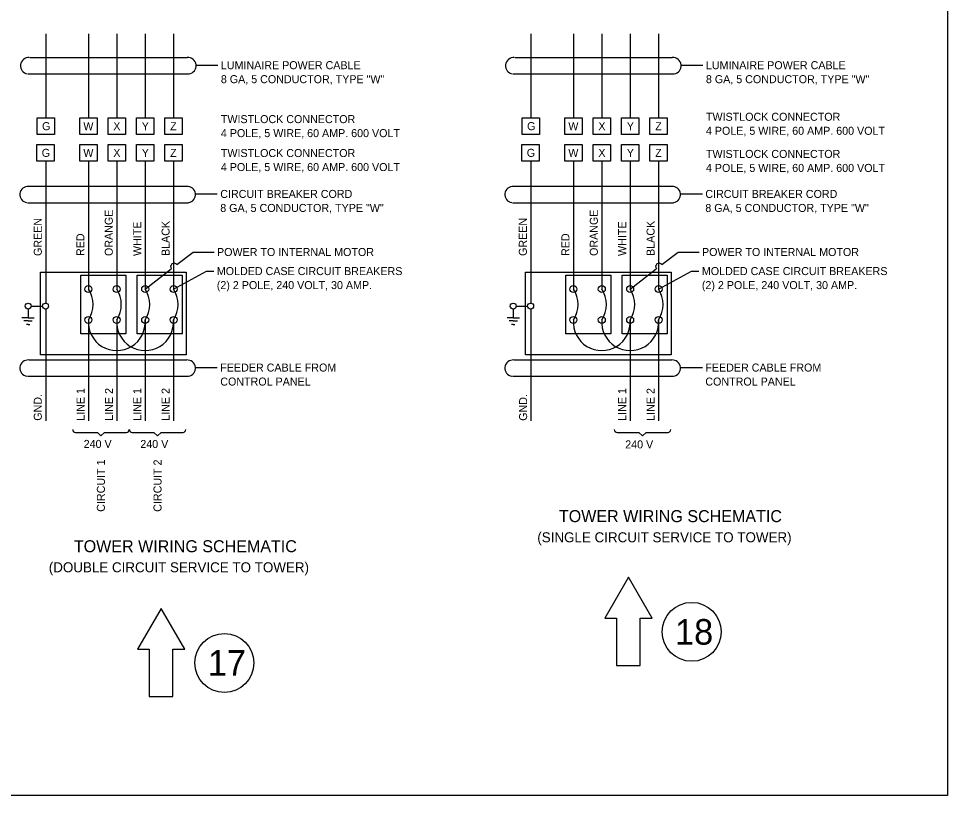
# Model space of a CAD drawing. Extents: x 99981 to 128681, y 99783 to 102182.
# Drawn here: x 122189 to 123581, y 99887 to 101052 of the extents above; entities that cross this region are included whole.
import ezdxf

# ---------------------------------------------------------------- set-up
doc = ezdxf.new("R2010")
doc.units = 0
for name, color, linetype in [('Default', 7, 'Continuous'), ('Level 1', 7, 'Continuous'), ('RD Lighting', 7, 'Continuous')]:
    doc.layers.add(name, color=color, linetype=linetype)

msp = doc.modelspace()

# ---------------------------------------------------------------- linework, layer by layer
at = {"layer": 'Default'}
msp.add_lwpolyline([(120381.4, 102086.3), (123581.1, 102086.3), (123581.1, 99886.7), (120381.4, 99886.7)], close=True, dxfattribs=at)
at = {"layer": 'Level 1'}
for p, q in [((122229.5, 101028.7), (122229.5, 100903)), ((122293.3, 101028.7), (122293.3, 100903)), ((122335.9, 101028.7), (122335.9, 100903)), ((122378.5, 101028.7), (122378.5, 100903)), ((122421.1, 101028.7), (122421.1, 100903)), ((122956.6, 101028.7), (122956.6, 100903)), ((123020.4, 101028.7), (123020.4, 100903)), ((123063, 101028.7), (123063, 100903)), ((123105.5, 101028.7), (123105.5, 100903)), ((123148.1, 101028.7), (123148.1, 100903)), ((122205.7, 100993.2), (122441.6, 100993.2)), ((122932.7, 100993.2), (123168.7, 100993.2)), ((122454.8, 100981.8), (122487.5, 100981.8)), ((123181.8, 100981.8), (123214.6, 100981.8)), ((122203, 100968.7), (122444.3, 100968.7)), ((122930, 100968.7), (123171.4, 100968.7)), ((122229.5, 100837.6), (122229.5, 100625)), ((122293.3, 100837.6), (122293.3, 100646)), ((122335.9, 100837.6), (122335.9, 100646)), ((122378.5, 100837.6), (122378.5, 100646)), ((122421.1, 100837.6), (122421.1, 100646)), ((122956.6, 100837.6), (122956.6, 100625)), ((123020.4, 100837.6), (123020.4, 100646)), ((123063, 100837.6), (123063, 100646)), ((123105.5, 100837.6), (123105.5, 100646)), ((123148.1, 100837.6), (123148.1, 100646)), ((122204.8, 100800.1), (122440.7, 100800.1)), ((122931.8, 100800.1), (123167.8, 100800.1)), ((122453.9, 100788.7), (122486.6, 100788.7)), ((123181, 100788.7), (123213.7, 100788.7)), ((122202.1, 100775.6), (122443.4, 100775.6)), ((122929.1, 100775.6), (123170.5, 100775.6)), ((122426, 100682.7), (122450.5, 100701.6)), ((122450.5, 100701.6), (122481.7, 100701.6)), ((123153, 100682.7), (123177.5, 100701.6)), ((123177.5, 100701.6), (123208.7, 100701.6)), ((122282, 100666.9), (122349.3, 100666.9)), ((122282, 100578.9), (122282, 100666.9)), ((122349.3, 100666.9), (122349.3, 100578.9)), ((122378.5, 100646), (122417.7, 100676.3)), ((122421.1, 100646), (122470.5, 100673)), ((122470.5, 100673), (122481.4, 100673)), ((123009.1, 100666.9), (123076.4, 100666.9)), ((123009.1, 100578.9), (123009.1, 100666.9)), ((123076.4, 100666.9), (123076.4, 100578.9)), ((123105.5, 100646), (123144.7, 100676.3)), ((123148.1, 100646), (123197.5, 100673)), ((123197.5, 100673), (123208.5, 100673)), ((122203.1, 100615.8), (122203.1, 100603)), ((122207.6, 100620.5), (122224.8, 100620.5)), ((122229.5, 100615.2), (122229.5, 100448.3)), ((122930.2, 100615.8), (122930.2, 100603)), ((122934.6, 100620.5), (122951.8, 100620.5)), ((122956.6, 100615.2), (122956.6, 100448.3)), ((122203.1, 100603), (122193.8, 100603.1)), ((122203, 100598.2), (122196.8, 100598.2)), ((122203.1, 100603), (122212.3, 100603)), ((122203.1, 100598.2), (122209.3, 100598.2)), ((122293.6, 100599.9), (122293.6, 100448.3)), ((122336.2, 100599.9), (122336.2, 100448.3)), ((122378.5, 100599.8), (122378.5, 100448.3)), ((122421.1, 100599.8), (122421.1, 100448.3)), ((122930.1, 100603), (122920.9, 100603.1)), ((122930.1, 100598.2), (122923.9, 100598.2)), ((122930.2, 100603), (122939.4, 100603)), ((122930.2, 100598.2), (122936.4, 100598.2)), ((123105.5, 100599.8), (123105.5, 100448.3)), ((123148.1, 100599.8), (123148.1, 100448.3)), ((122203, 100593.1), (122200.4, 100593.1)), ((122203.1, 100593.1), (122205.8, 100593.1)), ((122930.1, 100593.1), (122927.4, 100593.1)), ((122930.2, 100593.1), (122932.8, 100593.1)), ((122349.3, 100578.9), (122282, 100578.9)), ((123076.4, 100578.9), (123009.1, 100578.9)), ((122204.8, 100539.7), (122440.7, 100539.7)), ((122453.9, 100528.3), (122486.6, 100528.3)), ((122931.8, 100539.7), (123167.8, 100539.7)), ((123181, 100528.3), (123213.7, 100528.3)), ((122202.1, 100515.2), (122443.4, 100515.2)), ((122929.1, 100515.2), (123170.5, 100515.2)), ((122273.9, 100431.1), (122306.8, 100431.1)), ((122306.8, 100431.1), (122312.1, 100425.8)), ((122317.5, 100431.1), (122312.1, 100425.8)), ((122317.5, 100431.1), (122350.3, 100431.1)), ((122358.8, 100431.1), (122391.6, 100431.1)), ((122391.6, 100431.1), (122397, 100425.7)), ((122402.3, 100431.1), (122397, 100425.7)), ((122402.3, 100431.1), (122435.2, 100431.1)), ((123085.8, 100431.1), (123118.7, 100431.1)), ((123118.7, 100431.1), (123124, 100425.7)), ((123129.4, 100431.1), (123124, 100425.7)), ((123129.4, 100431.1), (123162.3, 100431.1))]:
    msp.add_line(p, q, dxfattribs=at)
for points in [[(122216.5, 100903), (122242.5, 100903), (122242.5, 100877.7), (122216.5, 100877.7)], [(122280.3, 100903), (122306.4, 100903), (122306.4, 100877.7), (122280.3, 100877.7)], [(122322.9, 100903), (122348.9, 100903), (122348.9, 100877.7), (122322.9, 100877.7)], [(122365.5, 100903), (122391.5, 100903), (122391.5, 100877.7), (122365.5, 100877.7)], [(122408, 100903), (122434.1, 100903), (122434.1, 100877.7), (122408, 100877.7)], [(122943.5, 100903), (122969.6, 100903), (122969.6, 100877.7), (122943.5, 100877.7)], [(123007.4, 100903), (123033.4, 100903), (123033.4, 100877.7), (123007.4, 100877.7)], [(123050, 100903), (123076, 100903), (123076, 100877.7), (123050, 100877.7)], [(123092.5, 100903), (123118.6, 100903), (123118.6, 100877.7), (123092.5, 100877.7)], [(123135.1, 100903), (123161.1, 100903), (123161.1, 100877.7), (123135.1, 100877.7)], [(122216, 100862.9), (122242, 100862.9), (122242, 100837.6), (122216, 100837.6)], [(122280.3, 100862.9), (122306.4, 100862.9), (122306.4, 100837.6), (122280.3, 100837.6)], [(122322.9, 100862.9), (122348.9, 100862.9), (122348.9, 100837.6), (122322.9, 100837.6)], [(122365.5, 100862.9), (122391.5, 100862.9), (122391.5, 100837.6), (122365.5, 100837.6)], [(122408, 100862.9), (122434.1, 100862.9), (122434.1, 100837.6), (122408, 100837.6)], [(122943.1, 100862.9), (122969.1, 100862.9), (122969.1, 100837.6), (122943.1, 100837.6)], [(123007.4, 100862.9), (123033.4, 100862.9), (123033.4, 100837.6), (123007.4, 100837.6)], [(123050, 100862.9), (123076, 100862.9), (123076, 100837.6), (123050, 100837.6)], [(123092.5, 100862.9), (123118.6, 100862.9), (123118.6, 100837.6), (123092.5, 100837.6)], [(123135.1, 100862.9), (123161.1, 100862.9), (123161.1, 100837.6), (123135.1, 100837.6)], [(122221.4, 100671.4), (122440, 100671.4), (122440, 100547.5), (122221.4, 100547.5)], [(122366.4, 100666.9), (122433.7, 100666.9), (122433.7, 100578.9), (122366.4, 100578.9)], [(122948.5, 100671.4), (123167, 100671.4), (123167, 100547.5), (122948.5, 100547.5)], [(123093.5, 100666.9), (123160.8, 100666.9), (123160.8, 100578.9), (123093.5, 100578.9)]]:
    msp.add_lwpolyline(points, close=True, dxfattribs=at)
for centre, radius in [((122293.3, 100646), 5.24), ((122335.9, 100646), 5.24), ((122378.5, 100646), 5.24), ((122421.1, 100646), 5.24), ((123020.4, 100646), 5.24), ((123063, 100646), 5.24), ((123105.5, 100646), 5.24), ((123148.1, 100646), 5.24), ((122203.1, 100620.5), 4.47), ((122229.2, 100620.5), 4.47), ((122930.2, 100620.5), 4.47), ((122956.3, 100620.5), 4.47), ((122293.3, 100599.8), 5.24), ((122335.9, 100599.8), 5.24), ((122378.5, 100599.8), 5.24), ((122421.1, 100599.8), 5.24), ((123020.4, 100599.8), 5.24), ((123063, 100599.8), 5.24), ((123105.5, 100599.8), 5.24), ((123148.1, 100599.8), 5.24)]:
    msp.add_circle(centre, radius, dxfattribs=at)
for centre, radius, start, end in [((122203.9, 100980.9), 12.3, 85.7861, 261.6234), ((122442.5, 100980.9), 12.3, 278.3766, 94.2139), ((122930.9, 100980.9), 12.3, 85.7861, 261.6234), ((123169.6, 100980.9), 12.3, 278.3766, 94.2139), ((122203, 100787.8), 12.3, 85.7861, 261.6234), ((122441.6, 100787.8), 12.3, 278.3766, 94.2139), ((122930, 100787.8), 12.3, 85.7861, 261.6234), ((123168.7, 100787.8), 12.3, 278.3766, 94.2139), ((122421.8, 100679.5), 5.24, 38.1296, 217.1791), ((123148.9, 100679.5), 5.24, 38.1296, 217.1791), ((122257.8, 100622.9), 42.5, 327.1836, 33.0606), ((122300.3, 100622.9), 42.4, 327.0615, 32.9385), ((122342.9, 100622.9), 42.4, 327.0615, 32.9385), ((122385.4, 100622.9), 42.4, 327.0615, 32.9385), ((122984.8, 100622.9), 42.5, 327.1836, 33.0606), ((123027.4, 100622.9), 42.4, 327.0615, 32.9385), ((123069.9, 100622.9), 42.4, 327.0615, 32.9385), ((123112.5, 100622.9), 42.4, 327.0615, 32.9385), ((122335.9, 100596.4), 42.6, 175.318, 4.6724), ((122378.4, 100596.4), 42.6, 175.318, 4.6724), ((123062.9, 100596.4), 42.6, 175.318, 4.6724), ((123105.5, 100596.4), 42.6, 175.318, 4.6724), ((122203, 100527.4), 12.3, 85.7861, 261.6234), ((122441.6, 100527.4), 12.3, 278.3766, 94.2139), ((122930, 100527.4), 12.3, 85.7861, 261.6234), ((123168.7, 100527.4), 12.3, 278.3766, 94.2139), ((122274, 100435.3), 4.15, 181.1495, 270.7231), ((122350.4, 100435.3), 4.15, 269.2769, 358.8505), ((122358.9, 100435.3), 4.15, 181.1495, 270.7231), ((122435.3, 100435.3), 4.15, 269.2769, 358.8505), ((123085.9, 100435.3), 4.15, 181.1495, 270.7231), ((123162.3, 100435.3), 4.15, 269.2769, 358.8505)]:
    msp.add_arc(centre, radius, start, end, dxfattribs=at)
at = {"layer": 'RD Lighting'}
for points in [[(123102.9, 100213.8), (123067.5, 100152.3), (123085.2, 100152.3), (123085.2, 100081.4), (123120.7, 100081.4), (123120.7, 100152.3), (123138.4, 100152.3)], [(122402.5, 100167.2), (122367, 100105.8), (122384.7, 100105.8), (122384.7, 100034.8), (122420.2, 100034.8), (122420.2, 100105.8), (122438, 100105.8)]]:
    msp.add_lwpolyline(points, close=True, dxfattribs=at)
for centre in [(123197.8, 100132), (122497.3, 100085.4)]:
    msp.add_circle(centre, 44.2, dxfattribs=at)

# ---------------------------------------------------------------- texts
at = {"layer": 'Level 1'}
for s, height, p in [(' LUMINAIRE POWER CABLE', 12, (122487.5, 100975.8)), (' LUMINAIRE POWER CABLE', 12, (123214.6, 100975.8)), (' 8 GA, 5 CONDUCTOR, TYPE "W"', 12, (122487.5, 100954.8)), (' 8 GA, 5 CONDUCTOR, TYPE "W"', 12, (123214.6, 100954.8)), (' TWISTLOCK CONNECTOR', 12, (122487.5, 100894.9)), (' TWISTLOCK CONNECTOR', 12, (123214.6, 100898.4)), ('G', 12, (122223.9, 100884.3)), ('W', 12, (122285.8, 100884.3)), ('X', 12, (122330.7, 100884.3)), ('Y', 12, (122373.4, 100884.3)), ('Z', 12, (122415.9, 100884.3)), ('G', 12, (122951, 100884.3)), ('W', 12, (123012.8, 100884.3)), ('X', 12, (123057.8, 100884.3)), ('Y', 12, (123100.5, 100884.3)), ('Z', 12, (123143, 100884.3)), (' 4 POLE, 5 WIRE, 60 AMP. 600 VOLT', 12, (123214.6, 100877.4)), (' 4 POLE, 5 WIRE, 60 AMP. 600 VOLT', 12, (122487.5, 100873.9)), ('G', 12, (122223.4, 100844.3)), ('W', 12, (122285.8, 100844.3)), ('X', 12, (122330.7, 100844.3)), ('Y', 12, (122373.4, 100844.3)), ('Z', 12, (122415.9, 100844.3)), (' TWISTLOCK CONNECTOR', 12, (122487.5, 100844)), ('G', 12, (122950.5, 100844.3)), ('W', 12, (123012.8, 100844.3)), ('X', 12, (123057.8, 100844.3)), ('Y', 12, (123100.5, 100844.3)), ('Z', 12, (123143, 100844.3)), (' TWISTLOCK CONNECTOR', 12, (123214.6, 100842.7)), (' 4 POLE, 5 WIRE, 60 AMP. 600 VOLT', 12, (122487.5, 100823)), (' 4 POLE, 5 WIRE, 60 AMP. 600 VOLT', 12, (123214.6, 100821.7)), (' CIRCUIT BREAKER CORD', 12, (122486.6, 100782.7)), (' CIRCUIT BREAKER CORD', 12, (123213.7, 100782.7)), (' 8 GA, 5 CONDUCTOR, TYPE "W"', 12, (122486.6, 100761.7)), (' 8 GA, 5 CONDUCTOR, TYPE "W"', 12, (123213.7, 100761.7)), (' POWER TO INTERNAL MOTOR', 12, (122481.7, 100695.6)), (' POWER TO INTERNAL MOTOR', 12, (123208.7, 100695.6)), (' MOLDED CASE CIRCUIT BREAKERS', 12, (122481.4, 100667)), (' MOLDED CASE CIRCUIT BREAKERS', 12, (123208.5, 100667)), (' (2) 2 POLE, 240 VOLT, 30 AMP.', 12, (122481.4, 100646)), (' (2) 2 POLE, 240 VOLT, 30 AMP.', 12, (123208.5, 100646)), (' FEEDER CABLE FROM', 12, (122486.6, 100522.3)), (' FEEDER CABLE FROM', 12, (123213.7, 100522.3)), (' CONTROL PANEL', 12, (122486.6, 100501.3)), (' CONTROL PANEL', 12, (123213.7, 100501.3)), ('240 V', 12, (122286.3, 100407.8)), ('240 V', 12, (122371.2, 100407.7)), ('240 V', 12, (123098.1, 100407.1)), ('TOWER WIRING SCHEMATIC', 18, (122998.7, 100296.5)), ('(SINGLE CIRCUIT SERVICE TO TOWER)', 15, (122966.3, 100266.3)), ('TOWER WIRING SCHEMATIC', 18, (122271.6, 100251.4)), ('(DOUBLE CIRCUIT SERVICE TO TOWER)', 15, (122234, 100221.3))]:
    msp.add_text(s, height=height, dxfattribs=at).set_placement(p)
for s, p in [('ORANGE', (122329.9, 100695.6)), ('ORANGE', (123057, 100695.7)), ('GREEN', (122223.5, 100695.6)), ('GREEN', (122950.6, 100695.7)), ('WHITE', (122372.5, 100695.6)), ('BLACK', (122415.1, 100695.6)), ('WHITE', (123099.5, 100695.7)), ('BLACK', (123142.1, 100695.7)), ('RED', (122287.3, 100695.6)), ('RED', (123014.4, 100695.7)), ('GND.', (122223.5, 100448.6)), ('LINE 1', (122287.6, 100448.6)), ('LINE 2', (122330.2, 100448.6)), ('LINE 1', (122372.5, 100448.6)), ('LINE 2', (122415.1, 100448.6)), ('GND.', (122951, 100448.5)), ('LINE 1', (123099.5, 100448.5)), ('LINE 2', (123142.1, 100448.5)), ('CIRCUIT 1 ', (122318.1, 100312)), ('CIRCUIT 2 ', (122403, 100312))]:
    msp.add_text(s, height=12, rotation=90, dxfattribs=at).set_placement(p)
at = {"layer": 'RD Lighting'}
for s, p in [('18', (123172.9, 100112.8)), ('17', (122472.5, 100066.3))]:
    msp.add_text(s, height=38.31, dxfattribs=at).set_placement(p)

doc.saveas('drawing.dxf')
